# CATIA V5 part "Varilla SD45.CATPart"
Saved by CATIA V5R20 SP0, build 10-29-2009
Part number: Varilla SD45
Revision: ANY
Definition: UNKNOWN
Nomenclature: Varilla SD45
Source: Unknown
Bounding box of the stored display mesh (mm): x -8 to 8, y 0 to 250, z -8 to 8
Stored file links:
  C:\Users\Utente\Desktop\IO LAVORO\3D X SITO CF\CUMSA\3D files SD\SD 4528\Varilla SD45.CATPart
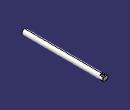
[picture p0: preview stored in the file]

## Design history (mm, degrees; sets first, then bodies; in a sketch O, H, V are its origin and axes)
Body1 "Cortar-Extruir2" (main body)
  Solid1: solid without history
